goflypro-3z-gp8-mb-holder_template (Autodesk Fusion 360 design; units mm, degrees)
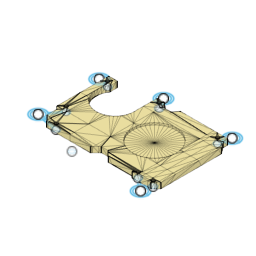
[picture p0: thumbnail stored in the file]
base_mesh_feature "Grundnetzelement"
modify "Ändern1"
modify "Ändern2"
sketch "Skizze" plane through (0, 0, 0) normal (0, 0, 1) x axis (1, 0, 0)
  line L1 (-0.3357, 17.7991) -> (-0.9702, 18.8981)
  line L2 (0.1339, 16.9858) -> (0.103, 17.0392)
  line L3 (-1.0193, 17.3831) -> (-1.6561, 18.4861)
  line L4 (-0.5589, 16.5858) -> (-0.562, 16.591)
  line L5 (27.1642, 17.4034) -> (27.3755, 18.3975)
  line L6 (27.9495, 17.2502) -> (28.1553, 18.2181)
  line L7 (28.8879, -17.0315) -> (28.8548, -17.2191)
  line L8 (29.6735, -17.1831) -> (29.635, -17.4013)
  line L9 (25.6902, -18.7693) -> (23.4957, -16.9278)
  line L10 (26.1894, -18.1439) -> (23.9858, -16.2948)
  line L11 (-16.7568, -15.4995) -> (-22.3589, -14.5117)
  line L12 (-16.58, -14.7183) -> (-22.2077, -13.726)
  line L13 (-20.5815, -7.4431) -> (-23.1796, -11.1536)
  line L14 (-21.2033, -6.9364) -> (-23.8132, -10.6637)
  line L15 (-21.5856, 14.033) -> (-22.2136, 14.2012)
  line L16 (-21.815, 13.2662) -> (-22.3823, 13.4183)
  circle C1 centre (-20.415, 13.265) radius 0.6
  circle C2 centre (-20.045, -6.15) radius 0.6
  circle C3 centre (-15.36, -15.405) radius 0.6
  circle C4 centre (22.68, -15.79) radius 0.6
  circle C5 centre (29.535, -15.79) radius 0.6
  circle C6 centre (0.02, 16.445) radius 0.6
  circle C7 centre (27.3, 16.01) radius 0.6
  circle C8 centre (-25.5, 14.5) radius 1.05
  circle C9 centre (-25.5, -13.5) radius 1.05
  circle C10 centre (-3, 21.5) radius 1.05
  circle C11 centre (28.5, 21.5) radius 1.05
  circle C12 centre (28.5, -20.5) radius 1.05
  circle C13 centre (-3, -20.5) radius 1.05
  circle C14 centre (-25.5, 14.5) radius 2.5
  circle C15 centre (-3, 21.5) radius 2.5
  circle C16 centre (28.5, 21.5) radius 2.5
  circle C17 centre (-25.5, -13.5) radius 2.5
  circle C18 centre (28.5, -20.5) radius 2.5
  circle C19 centre (28.5, -20.5) radius 3.3
  circle C20 centre (-25.5, -13.5) radius 3.3
  circle C21 centre (-25.5, 14.5) radius 3.3
  circle C22 centre (-3, 21.5) radius 3.3
  circle C23 centre (28.5, 21.5) radius 3.3
  circle C24 centre (27.3, 16.01) radius 1.4
  circle C25 centre (0.02, 16.445) radius 1.4
  circle C26 centre (29.535, -15.79) radius 1.4
  circle C27 centre (22.68, -15.79) radius 1.4
  circle C28 centre (-15.36, -15.405) radius 1.4
  circle C29 centre (-20.045, -6.15) radius 1.4
  circle C30 centre (-20.415, 13.265) radius 1.4
  point P34 (-1.6561, 18.4861)
  point P35 (-0.9702, 18.8981)
  point P36 (-0.3357, 17.7991)
  point P37 (0.103, 17.0392)
  point P38 (-1.0193, 17.3831)
  point P39 (-0.562, 16.591)
  point P40 (27.3755, 18.3975)
  point P41 (28.1553, 18.2181)
  point P42 (27.9495, 17.2502)
  point P43 (27.1642, 17.4034)
  point P44 (29.6735, -17.1831)
  point P45 (28.8879, -17.0315)
  point P46 (28.8548, -17.2191)
  point P47 (29.635, -17.4013)
  point P48 (23.9858, -16.2948)
  point P49 (23.4957, -16.9278)
  point P50 (25.6902, -18.7693)
  point P51 (26.1894, -18.1439)
  point P52 (-22.2077, -13.726)
  point P53 (-22.3589, -14.5117)
  point P54 (-16.7568, -15.4995)
  point P55 (-16.58, -14.7183)
  point P56 (-20.5815, -7.4431)
  point P57 (-21.2033, -6.9364)
  point P58 (-23.1796, -11.1536)
  point P59 (-23.8132, -10.6637)
  point P61 (-21.815, 13.2662)
  point P62 (-21.5856, 14.033)
  point P63 (-22.2136, 14.2012)
  point P64 (-22.3823, 13.4183)
  concentric C8 C14
  concentric C10 C15
  concentric C11 C16
  concentric C9 C17
  concentric C12 C18
  concentric C18 C19
  concentric C9 C20
  concentric C8 C21
  concentric C10 C22
  concentric C11 C23
  concentric C7 C24
  concentric C6 C25
  concentric C5 C26
  concentric C4 C27
  concentric C3 C28
  concentric C2 C29
  coincident C22 P34
  coincident C22 P35
  coincident C25 P36
  coincident C6 P37
  collinear L1 L2
  coincident C25 P38
  coincident C6 P39
  collinear L3 L4
  coincident C23 P40
  coincident C23 P41
  coincident C24 P42
  coincident C24 P43
  coincident C26 P44
  coincident C26 P45
  coincident C19 P46
  coincident C19 P47
  coincident C27 P48
  coincident C27 P49
  coincident C19 P50
  coincident C19 P51
  coincident C20 P52
  coincident C20 P53
  coincident C28 P54
  coincident C28 P55
  coincident C29 P56
  coincident C29 P57
  coincident C20 P58
  coincident C20 P59
  concentric C1 C30
  coincident C30 P61
  coincident C30 P62
  coincident C21 P63
  coincident C21 P64
  dimension "d1" diameter C1 = 1.2
  dimension "d2" diameter C2 = 1.2
  dimension "d3" diameter C3 = 1.2
  dimension "d4" diameter C4 = 1.2
  dimension "d5" diameter C5 = 1.2
  dimension "d6" diameter C6 = 1.2
  dimension "d7" diameter C7 = 1.2
  dimension "d12" diameter C10 = 2.1
  dimension "d13" diameter C8 = 2.1
  dimension "d14" diameter C9 = 2.1
  dimension "d15" diameter C14 = 5
  dimension "d16" diameter C15 = 5
  dimension "d17" diameter C16 = 5
  dimension "d18" diameter C17 = 5
  dimension "d19" diameter C18 = 5
  dimension "d20" diameter C19 = 6.6
  dimension "d21" diameter C20 = 6.6
  dimension "d22" diameter C21 = 6.6
  dimension "d23" diameter C22 = 6.6
  dimension "d24" diameter C23 = 6.6
  dimension "d26" diameter C24 = 2.8
  dimension "d27" diameter C25 = 2.8
  dimension "d28" diameter C26 = 2.8
  dimension "d29" diameter C27 = 2.8
  dimension "d30" diameter C28 = 2.8
  dimension "d31" diameter C29 = 2.8
  dimension "d32" diameter C30 = 2.8
  dimension "d10" R-Pattern1-uDistance = 31.5
  dimension "d11" R-Pattern1-vDistance = -42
